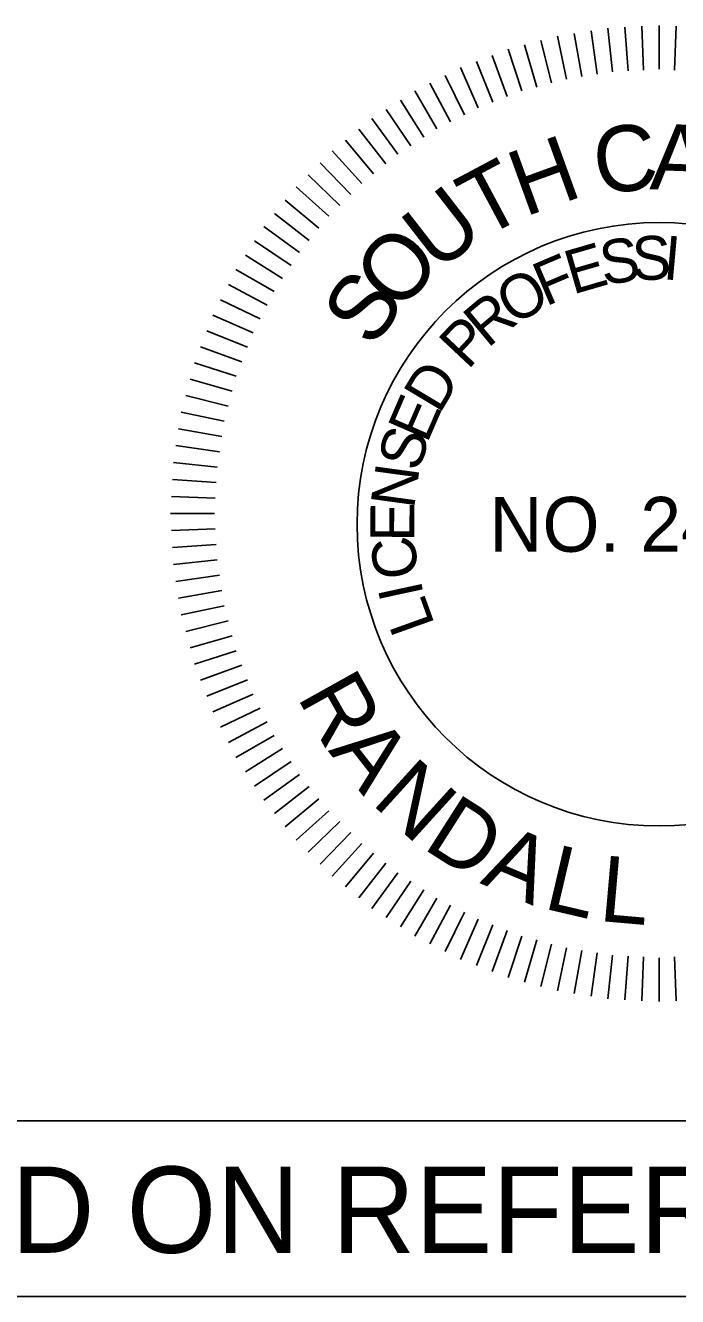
# Model space of a CAD drawing. Extents: x 1964850 to 1967424, y 1116563 to 1122204.
# Drawn here: x 1966441.1 to 1966494, y 1121679.1 to 1121782.3 of the extents above; entities that cross this region are included whole.
import ezdxf

# ---------------------------------------------------------------- set-up
doc = ezdxf.new("R2010")
doc.units = 0
doc.layers.add('RD_Sketch1', color=7, linetype='Continuous')
doc.layers.add('RD_TX_PEShield', color=7, linetype='Continuous')

msp = doc.modelspace()

# ---------------------------------------------------------------- linework, layer by layer
at = {"layer": 'RD_Sketch1'}
msp.add_lwpolyline([(1966266.73, 1121693.39), (1966567.16, 1121693.39), (1966567.16, 1121679.13), (1966266.73, 1121679.13)], close=True, dxfattribs=at)
at = {"layer": 'RD_TX_PEShield'}
for p, q in [((1966487.45, 1121778.33), (1966486.96, 1121781.85)), ((1966487.45, 1121778.33), (1966486.96, 1121781.85)), ((1966488.7, 1121778.52), (1966488.32, 1121782.06)), ((1966488.7, 1121778.52), (1966488.32, 1121782.06)), ((1966489.95, 1121778.59), (1966489.7, 1121782.14)), ((1966489.95, 1121778.59), (1966489.7, 1121782.14)), ((1966491.21, 1121778.65), (1966491.08, 1121782.21)), ((1966491.21, 1121778.65), (1966491.08, 1121782.21)), ((1966492.46, 1121778.72), (1966492.46, 1121782.28)), ((1966492.46, 1121778.72), (1966492.46, 1121782.28)), ((1966493.72, 1121778.65), (1966493.84, 1121782.21)), ((1966493.72, 1121778.65), (1966493.84, 1121782.21)), ((1966482.54, 1121777.28), (1966481.56, 1121780.7)), ((1966482.54, 1121777.28), (1966481.56, 1121780.7)), ((1966483.75, 1121777.61), (1966482.89, 1121781.06)), ((1966483.75, 1121777.61), (1966482.89, 1121781.06)), ((1966484.97, 1121777.93), (1966484.23, 1121781.41)), ((1966484.97, 1121777.93), (1966484.23, 1121781.41)), ((1966486.21, 1121778.13), (1966485.59, 1121781.63)), ((1966486.21, 1121778.13), (1966485.59, 1121781.63)), ((1966480.15, 1121776.51), (1966478.93, 1121779.85)), ((1966480.15, 1121776.51), (1966478.93, 1121779.85)), ((1966481.33, 1121776.96), (1966480.23, 1121780.34)), ((1966481.33, 1121776.96), (1966480.23, 1121780.34)), ((1966477.8, 1121775.6), (1966476.36, 1121778.86)), ((1966477.8, 1121775.6), (1966476.36, 1121778.86)), ((1966478.98, 1121776.05), (1966477.65, 1121779.35)), ((1966478.98, 1121776.05), (1966477.65, 1121779.35)), ((1966475.56, 1121774.46), (1966473.89, 1121777.6)), ((1966475.56, 1121774.46), (1966473.89, 1121777.6)), ((1966476.68, 1121775.03), (1966475.12, 1121778.23)), ((1966476.68, 1121775.03), (1966475.12, 1121778.23)), ((1966474.44, 1121773.89), (1966472.66, 1121776.97)), ((1966474.44, 1121773.89), (1966472.66, 1121776.97)), ((1966473.39, 1121773.21), (1966471.5, 1121776.22)), ((1966473.39, 1121773.21), (1966471.5, 1121776.22)), ((1966471.28, 1121771.84), (1966469.18, 1121774.72)), ((1966471.28, 1121771.84), (1966469.18, 1121774.72)), ((1966472.33, 1121772.52), (1966470.34, 1121775.47)), ((1966472.33, 1121772.52), (1966470.34, 1121775.47)), ((1966470.3, 1121771.04), (1966468.11, 1121773.85)), ((1966470.3, 1121771.04), (1966468.11, 1121773.85)), ((1966469.32, 1121770.25), (1966467.04, 1121772.98)), ((1966469.32, 1121770.25), (1966467.04, 1121772.98)), ((1966468.35, 1121769.46), (1966465.96, 1121772.11)), ((1966468.35, 1121769.46), (1966465.96, 1121772.11)), ((1966467.46, 1121768.57), (1966464.99, 1121771.13)), ((1966467.46, 1121768.57), (1966464.99, 1121771.13)), ((1966466.57, 1121767.68), (1966464.01, 1121770.15)), ((1966466.57, 1121767.68), (1966464.01, 1121770.15)), ((1966465.68, 1121766.79), (1966463.03, 1121769.18)), ((1966465.68, 1121766.79), (1966463.03, 1121769.18)), ((1966464.89, 1121765.82), (1966462.16, 1121768.1)), ((1966464.89, 1121765.82), (1966462.16, 1121768.1)), ((1966464.09, 1121764.84), (1966461.29, 1121767.03)), ((1966464.09, 1121764.84), (1966461.29, 1121767.03)), ((1966463.3, 1121763.86), (1966460.42, 1121765.95)), ((1966463.3, 1121763.86), (1966460.42, 1121765.95)), ((1966462.62, 1121762.81), (1966459.67, 1121764.79)), ((1966462.62, 1121762.81), (1966459.67, 1121764.79)), ((1966461.93, 1121761.75), (1966458.92, 1121763.64)), ((1966461.93, 1121761.75), (1966458.92, 1121763.64)), ((1966461.25, 1121760.7), (1966458.16, 1121762.48)), ((1966461.25, 1121760.7), (1966458.16, 1121762.48)), ((1966460.68, 1121759.58), (1966457.54, 1121761.25)), ((1966460.68, 1121759.58), (1966457.54, 1121761.25)), ((1966460.11, 1121758.46), (1966456.91, 1121760.02)), ((1966460.11, 1121758.46), (1966456.91, 1121760.02)), ((1966459.54, 1121757.34), (1966456.28, 1121758.78)), ((1966459.54, 1121757.34), (1966456.28, 1121758.78)), ((1966459.08, 1121756.16), (1966455.79, 1121757.49)), ((1966459.08, 1121756.16), (1966455.79, 1121757.49)), ((1966458.63, 1121754.99), (1966455.29, 1121756.2)), ((1966458.63, 1121754.99), (1966455.29, 1121756.2)), ((1966458.18, 1121753.81), (1966454.8, 1121754.91)), ((1966458.18, 1121753.81), (1966454.8, 1121754.91)), ((1966457.86, 1121752.6), (1966454.44, 1121753.58)), ((1966457.86, 1121752.6), (1966454.44, 1121753.58)), ((1966457.53, 1121751.38), (1966454.08, 1121752.24)), ((1966457.53, 1121751.38), (1966454.08, 1121752.24)), ((1966457.21, 1121750.17), (1966453.72, 1121750.91)), ((1966457.21, 1121750.17), (1966453.72, 1121750.91)), ((1966457.01, 1121748.93), (1966453.51, 1121749.54)), ((1966457.01, 1121748.93), (1966453.51, 1121749.54)), ((1966456.81, 1121747.69), (1966453.29, 1121748.18)), ((1966456.81, 1121747.69), (1966453.29, 1121748.18)), ((1966456.62, 1121746.44), (1966453.08, 1121746.81)), ((1966456.62, 1121746.44), (1966453.08, 1121746.81)), ((1966456.55, 1121745.19), (1966453, 1121745.43)), ((1966456.55, 1121745.19), (1966453, 1121745.43)), ((1966456.48, 1121743.93), (1966452.93, 1121744.06)), ((1966456.48, 1121743.93), (1966452.93, 1121744.06)), ((1966456.42, 1121742.68), (1966452.86, 1121742.68)), ((1966456.42, 1121742.68), (1966452.86, 1121742.68)), ((1966456.48, 1121741.42), (1966452.93, 1121741.29)), ((1966456.48, 1121741.42), (1966452.93, 1121741.29)), ((1966456.55, 1121740.16), (1966453, 1121739.92)), ((1966456.55, 1121740.16), (1966453, 1121739.92)), ((1966456.62, 1121738.91), (1966453.08, 1121738.54)), ((1966456.62, 1121738.91), (1966453.08, 1121738.54)), ((1966456.81, 1121737.66), (1966453.29, 1121737.17)), ((1966456.81, 1121737.66), (1966453.29, 1121737.17)), ((1966457.01, 1121736.42), (1966453.51, 1121735.81)), ((1966457.01, 1121736.42), (1966453.51, 1121735.81)), ((1966457.21, 1121735.18), (1966453.72, 1121734.44)), ((1966457.21, 1121735.18), (1966453.72, 1121734.44)), ((1966457.53, 1121733.97), (1966454.08, 1121733.11)), ((1966457.53, 1121733.97), (1966454.08, 1121733.11)), ((1966457.86, 1121732.75), (1966454.44, 1121731.77)), ((1966457.86, 1121732.75), (1966454.44, 1121731.77)), ((1966458.18, 1121731.54), (1966454.8, 1121730.44)), ((1966458.63, 1121730.36), (1966455.29, 1121729.15)), ((1966458.63, 1121730.36), (1966455.29, 1121729.15)), ((1966459.08, 1121729.19), (1966455.79, 1121727.86)), ((1966459.08, 1121729.19), (1966455.79, 1121727.86)), ((1966459.54, 1121728.01), (1966456.28, 1121726.57)), ((1966459.54, 1121728.01), (1966456.28, 1121726.57)), ((1966460.11, 1121726.89), (1966456.91, 1121725.33)), ((1966460.11, 1121726.89), (1966456.91, 1121725.33)), ((1966460.68, 1121725.77), (1966457.54, 1121724.1)), ((1966460.68, 1121725.77), (1966457.54, 1121724.1)), ((1966461.25, 1121724.65), (1966458.16, 1121722.87)), ((1966461.25, 1121724.65), (1966458.16, 1121722.87)), ((1966461.93, 1121723.6), (1966458.92, 1121721.71)), ((1966461.93, 1121723.6), (1966458.92, 1121721.71)), ((1966462.62, 1121722.54), (1966459.67, 1121720.56)), ((1966462.62, 1121722.54), (1966459.67, 1121720.56)), ((1966463.3, 1121721.49), (1966460.42, 1121719.4)), ((1966463.3, 1121721.49), (1966460.42, 1121719.4)), ((1966464.09, 1121720.51), (1966461.29, 1121718.32)), ((1966464.09, 1121720.51), (1966461.29, 1121718.32)), ((1966464.89, 1121719.53), (1966462.16, 1121717.25)), ((1966464.89, 1121719.53), (1966462.16, 1121717.25)), ((1966465.68, 1121718.56), (1966463.03, 1121716.17)), ((1966465.68, 1121718.56), (1966463.03, 1121716.17)), ((1966466.57, 1121717.67), (1966464.01, 1121715.2)), ((1966466.57, 1121717.67), (1966464.01, 1121715.2)), ((1966467.46, 1121716.78), (1966464.99, 1121714.22)), ((1966467.46, 1121716.78), (1966464.99, 1121714.22)), ((1966468.35, 1121715.89), (1966465.96, 1121713.24)), ((1966468.35, 1121715.89), (1966465.96, 1121713.24)), ((1966469.32, 1121715.1), (1966467.04, 1121712.37)), ((1966469.32, 1121715.1), (1966467.04, 1121712.37)), ((1966470.3, 1121714.31), (1966468.11, 1121711.5)), ((1966470.3, 1121714.31), (1966468.11, 1121711.5)), ((1966471.28, 1121713.51), (1966469.18, 1121710.63)), ((1966471.28, 1121713.51), (1966469.18, 1121710.63)), ((1966472.33, 1121712.83), (1966470.34, 1121709.88)), ((1966472.33, 1121712.83), (1966470.34, 1121709.88)), ((1966473.39, 1121712.14), (1966471.5, 1121709.13)), ((1966473.39, 1121712.14), (1966471.5, 1121709.13)), ((1966474.44, 1121711.46), (1966472.66, 1121708.38)), ((1966474.44, 1121711.46), (1966472.66, 1121708.38)), ((1966475.56, 1121710.89), (1966473.89, 1121707.75)), ((1966475.56, 1121710.89), (1966473.89, 1121707.75)), ((1966476.68, 1121710.32), (1966475.12, 1121707.12)), ((1966476.68, 1121710.32), (1966475.12, 1121707.12)), ((1966477.8, 1121709.75), (1966476.36, 1121706.49)), ((1966477.8, 1121709.75), (1966476.36, 1121706.49)), ((1966478.98, 1121709.3), (1966477.65, 1121706)), ((1966478.98, 1121709.3), (1966477.65, 1121706)), ((1966480.15, 1121708.85), (1966478.93, 1121705.5)), ((1966480.15, 1121708.85), (1966478.93, 1121705.5)), ((1966481.33, 1121708.39), (1966480.23, 1121705.01)), ((1966481.33, 1121708.39), (1966480.23, 1121705.01)), ((1966482.54, 1121708.07), (1966481.56, 1121704.65)), ((1966482.54, 1121708.07), (1966481.56, 1121704.65)), ((1966483.75, 1121707.74), (1966482.89, 1121704.29)), ((1966483.75, 1121707.74), (1966482.89, 1121704.29)), ((1966484.97, 1121707.42), (1966484.23, 1121703.94)), ((1966484.97, 1121707.42), (1966484.23, 1121703.94)), ((1966486.21, 1121707.22), (1966485.59, 1121703.72)), ((1966486.21, 1121707.22), (1966485.59, 1121703.72)), ((1966487.45, 1121707.02), (1966486.96, 1121703.5)), ((1966487.45, 1121707.02), (1966486.96, 1121703.5)), ((1966488.7, 1121706.83), (1966488.32, 1121703.29)), ((1966488.7, 1121706.83), (1966488.32, 1121703.29)), ((1966489.95, 1121706.76), (1966489.7, 1121703.21)), ((1966489.95, 1121706.76), (1966489.7, 1121703.21)), ((1966491.21, 1121706.7), (1966491.08, 1121703.14)), ((1966491.21, 1121706.7), (1966491.08, 1121703.14)), ((1966492.46, 1121706.63), (1966492.46, 1121703.07)), ((1966492.46, 1121706.63), (1966492.46, 1121703.07)), ((1966493.72, 1121706.7), (1966493.84, 1121703.14)), ((1966493.72, 1121706.7), (1966493.84, 1121703.14))]:
    msp.add_line(p, q, dxfattribs=at)
msp.add_circle((1966492.46, 1121741.8), 24.48, dxfattribs=at)

# ---------------------------------------------------------------- texts
at = {"layer": 'RD_Sketch1'}
msp.add_text('ALIGNMENT CONTROL CAN BE FOUND ON REFERENCE SHEET', height=7, dxfattribs=at).set_placement((1966270.38, 1121682.68))
at = {"layer": 'RD_TX_PEShield'}
for s, height, rotation, p in [('C', 5.34, 6.8832, (1966487.46, 1121768.53)), ('A', 5.34, 357.9448, (1966491.67, 1121768.99)), ('H', 5.34, 19.9102, (1966481.56, 1121766.72)), ('T', 5.34, 28.0947, (1966478.12, 1121764.91)), ('U', 5.34, 37.7726, (1966474.44, 1121762.17)), ('O', 5.34, 47.4504, (1966471.27, 1121758.85)), ('S', 3.56, 1.79, (1966490.31, 1121761.59)), ('I', 3.56, 354.889, (1966492.71, 1121761.7)), ('E', 3.56, 16.1843, (1966485.46, 1121760.43)), ('S', 3.56, 8.6909, (1966487.95, 1121761.19)), ('F', 3.56, 23.0853, (1966483.27, 1121759.45)), ('S', 5.34, 54.9027, (1966469.24, 1121755.96)), ('O', 3.56, 31.7869, (1966480.71, 1121757.86)), ('R', 3.56, 39.8902, (1966478.56, 1121756.04)), ('P', 3.56, 46.7912, (1966476.95, 1121754.27)), ('D', 3.56, 59.074, (1966474.65, 1121750.68)), ('E', 3.56, 66.5674, (1966473.64, 1121748.29)), ('S', 3.56, 73.4683, (1966473, 1121745.98)), ('N', 3.56, 82.17, (1966472.59, 1121742.98)), ('E', 3.56, 89.6633, (1966472.61, 1121740.38)), ('C', 3.56, 97.7667, (1966473.01, 1121737.6)), ('I', 3.56, 102.2511, (1966473.39, 1121736.09)), ('L', 3.56, 109.7445, (1966474.3, 1121733.65)), ('R', 5.34, 299.1493, (1966463.06, 1121727.82)), ('A', 5.34, 308.0877, (1966465.59, 1121723.42)), ('N', 5.34, 317.7655, (1966469.06, 1121719.17)), ('D', 5.34, 327.4433, (1966473.2, 1121715.56)), ('A', 5.34, 337.1212, (1966477.88, 1121712.69)), ('L', 5.34, 346.799, (1966482.98, 1121710.65)), ('L', 5.34, 354.9835, (1966487.51, 1121709.62))]:
    msp.add_text(s, height=height, rotation=rotation, dxfattribs=at).set_placement(p)
msp.add_text('NO. 24265', height=4.45, dxfattribs=at).set_placement((1966478.71, 1121739.57))

doc.saveas('drawing.dxf')
